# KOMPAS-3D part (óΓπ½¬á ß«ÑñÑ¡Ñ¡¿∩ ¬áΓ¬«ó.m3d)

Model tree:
1. Эскиз:1
2. Операция выдавливания:1
     Расстояние 1 = 8
3. Эскиз:2
4. Вырезать элемент выдавливания:1
     Расстояние 1 = 10
5. Скругление:1
     Радиус = 0.1
6. Скругление:2
     Радиус = 0.1

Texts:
  втулка соеденения катков
  Сплав АЛ8  ГОСТ 1583-93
